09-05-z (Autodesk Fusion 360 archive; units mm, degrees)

design "09-05-z" references "09-PIN", "09-KOTEI", "09-KADOU"
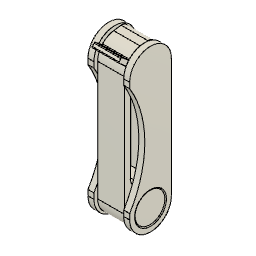
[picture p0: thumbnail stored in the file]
component_insert "コンポーネントの挿入1" alignOffsetZ 0
ground "固定"
component_insert "コンポーネントの挿入2"
joint "アセンブリ1" alignAngle 0 alignOffsetX 0 alignOffsetY 0 alignOffsetZ 0
component_insert "コンポーネントの挿入3"
joint "アセンブリ2" alignAngle 0 alignOffsetX 0 alignOffsetY 0 alignOffsetZ 0
component_insert "コンポーネントの挿入4"
joint "アセンブリ4" alignAngle 0 alignOffsetX 0 alignOffsetY 0 alignOffsetZ 0

design "09-KADOU"
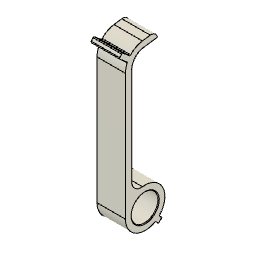
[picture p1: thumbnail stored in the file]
sketch "スケッチ1" plane through (0, 0, 0) normal (1, 0, 0) x axis (0, 0, -1)
  circle C1 centre (0, 0) radius 6.25
  point P1 (0, 0)
  point P2 (0, 0)
  coincident P1 P2
  dimension "d1" diameter C1 = 12.5
extrude "押し出し1" new body sketch "スケッチ1" distance 9
sketch "スケッチ2" plane through (0, 0, 0) normal (1, 0, 0) x axis (0, 0, -1)
  line L1 (-4.25, 0) -> (-4.25, 40)
  line L2 (-6.25, 0) -> (-4.25, 0)
  line L3 (-6.25, 40) -> (-6.25, 0)
  line L4 (3.8647, 44.8349) -> (-0.5915, 44.2086)
  line L5 (3.5864, 46.8155) -> (3.8647, 44.8349)
  line L6 (-0.8698, 46.1892) -> (3.5864, 46.8155)
  circle C1 centre (0, 0) radius 6.25
  arc A1 centre (0, 40) radius 4.25 clockwise from (-4.25, 40) to (-0.5915, 44.2086)
  arc A2 centre (0, 40) radius 6.25 clockwise from (-6.25, 40) to (-0.8698, 46.1892)
  point P1 (0, 0)
  point P8 (0, 40)
  point P12 (0, 40)
  vertical L1
  horizontal L2
  vertical L3
  coincident P1 L2
  tangent L3 C1
  perpendicular L4 L5
  perpendicular L5 L6
  coincident P8 P12
  vertical P1 P8
  tangent L1 A1
  tangent A1 L4
  tangent L3 A2
  dimension "d5" distance L1 L3 = 2
  dimension "d18" distance L4 L6 = 2
  dimension "d21" distance P8 L5 = 4.5
  dimension "d22" angle L1 L4 = 98
  dimension "d54" distance P1 P12 = 40
extrude "押し出し2" add sketch "スケッチ2" profile of L1 L3 C1 distance 9
sketch "スケッチ4" plane through (0, 0, 0) normal (1, 0, 0) x axis (0, 0, -1)
  line L1 (5.3033, -5.3033) -> (0, 0)
  line L2 (4.2426, -6.364) -> (5.3033, -5.3033)
  line L3 (-1.0607, -1.0607) -> (4.2426, -6.364)
  line L4 (0, 0) -> (-1.0607, -1.0607)
  line L5 (-22.5, 0) -> (-1.75, 0)
  point P1 (0, 0)
  point P2 (0, 0)
  perpendicular L1 L2
  parallel L1 L3
  parallel L2 L4
  coincident P1 P2
  dimension "d24" angle L1 L5 = 45
  dimension "d25" distance L2 L4 = 7.5
  dimension "d26" distance L1 L3 = 1.5
extrude "押し出し4" add sketch "スケッチ4" profile of L1 L2 L3 L4 distance 9
joint_origin "JointOrigin1" OffsetX 0 OffsetY 0 OffsetZ 0 AngleZ 0
sketch "スケッチ5" plane through (0, 0, 0) normal (1, 0, 0) x axis (0, 0, -1)
  line L1 (0, 40) -> (-7.2774, 46.1065)
  line L2 (-0.9642, 38.8509) -> (0, 40)
  line L3 (-8.2416, 44.9574) -> (-0.9642, 38.8509)
  line L4 (-7.2774, 46.1065) -> (-8.2416, 44.9574)
  line L5 (0, 22.5) -> (0, 1.75)
  arc A1 centre (0, 40) radius 4.25 clockwise from (-4.25, 40) to (-0.5915, 44.2086)
  point P3 (0, 40)
  point P8 (0, 40)
  perpendicular L1 L2
  parallel L1 L3
  parallel L2 L4
  coincident P3 P8
  dimension "d33" angle L1 L5 = 50
  dimension "d34" distance L1 L3 = 1.5
  dimension "d35" distance L2 L4 = 9.5
extrude "押し出し5" add sketch "スケッチ5" profile of L1 L3 L4 A1 distance 9
fillet "フィレット3" radius 2
sketch "スケッチ6" plane through (0, 43.4339, 6.1042) normal (0, -0.9903, -0.1392) x axis (-1, 0, 0)
  line L1 (-4.5, 10.0669) -> (4.5, 10.0669)
  line L2 (-4.5, 5.5669) -> (-4.5, 10.0669)
  line L3 (4.5, 5.5669) -> (-4.5, 5.5669)
  line L4 (4.5, 10.0669) -> (4.5, 5.5669)
  circle C1 centre (0, 8.0669) radius 0.75
  point P1 (0, 0)
  point P6 (0, 8.0669)
  vertical P1 P6
  dimension "d40" distance L1 P6 = 2
  dimension "d41" diameter C1 = 1.5
extrude "押し出し6" add sketch "スケッチ6" profile of C1 along normal blind 0.7
fillet "フィレット4" radius 0.6
fillet "フィレット5" radius 3
fillet "フィレット6" radius 0.3
hole "穴" HoleDepth 9 HoleDiameter 8.5 TipAngle 118
chamfer "面取り" distance 0.2

design "09-PIN"
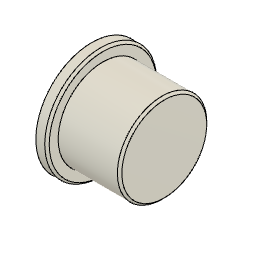
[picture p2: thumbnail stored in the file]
sketch "スケッチ" plane through (0, 0, 0) normal (0, 0, 1) x axis (1, 0, 0)
  line L1 (0, 5) -> (0, 0)
  line L2 (1, 5) -> (0, 5)
  line L3 (1, 4) -> (1, 5)
  line L4 (6.5, 4) -> (1, 4)
  line L5 (6.5, 0) -> (6.5, 4)
  line L6 (0, 0) -> (6.5, 0)
  point P1 (0, 0)
  point P2 (0, 0)
  point P8 (0, 0)
  point P3 (0, 5)
  point P4 (1, 5)
  point P5 (1, 4)
  point P6 (6.5, 4)
  coincident P1 P2
  vertical L1
  perpendicular L1 L2
  perpendicular L2 L3
  perpendicular L3 L4
  perpendicular L4 L5
  coincident P1 P8
  horizontal L6
  dimension "d1" = 8
  dimension "d2" = 10
  dimension "d3" distance P3 P4 = 1
  dimension "d4" distance P5 P6 = 5.5
revolve "回転" sketch "スケッチ" AlongAngle 360
chamfer "面取り" distance 0.2

design "09-KOTEI"
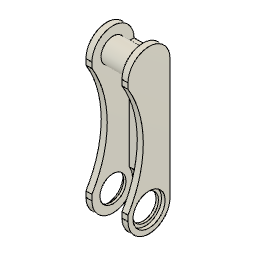
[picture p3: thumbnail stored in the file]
sketch "スケッチ1" plane through (0, 0, 0) normal (1, 0, 0) x axis (0, 0, -1)
  circle C1 centre (0, 40) radius 4
  point P1 (0, 0)
  point P2 (0, 40)
  vertical P1 P2
  dimension "d1" diameter C1 = 8
  dimension "d29" distance P1 P2 = 40
extrude "押し出し1" new body sketch "スケッチ1" + "スケッチ5" profile of S1:C1 distance 10
sketch "スケッチ2" plane through (5, 0, 0) normal (1, 0, 0) x axis (0, 0, -1)
  line L1 (-7, 0) -> (-7, 40)
  line L2 (7, 40) -> (7, 0)
  line L3 (0, 0) -> (0, 40)
  circle C1 centre (0, 40) radius 4
  arc A1 centre (0, 0) radius 7 clockwise from (7, 0) to (-7, 0)
  arc A2 centre (0, 40) radius 7 clockwise from (-7, 40) to (7, 40)
  point P7 (0, 40)
  point P9 (0, 40)
  point P8 (0, 0)
  tangent L1 A1
  tangent A1 L2
  parallel L1 L2
  tangent L2 A2
  tangent L1 A2
  vertical L3
  coincident P7 P9
  concentric C1 A2
  dimension "d4" radius A2 = 7
  dimension "d5" distance P7 P8 = 40
extrude "押し出し2" add sketch "スケッチ2" profile of C1 L1 A1 L2 A2 along normal blind 2
mirror "ミラー" sketch "スケッチ5" mirrorStitchTolerance 0.1
sketch "スケッチ3" plane through (0, 0, 0) normal (1, 0, 0) x axis (0, 0, -1)
  line L1 (7, 40) -> (5.4, 40)
  line L2 (7, 0) -> (7, 40)
  line L3 (5.4, 0) -> (7, 0)
  line L4 (5.4, 40) -> (5.4, 0)
  point P3 (7, 40)
  point P6 (7, 40)
  point P4 (7, 0)
  point P7 (7, 0)
  horizontal L1
  vertical L2
  horizontal L3
  vertical L4
  coincident P3 P6
  coincident P4 P7
  dimension "d10" distance L2 L4 = 1.6
extrude "押し出し3" add sketch "スケッチ3" distance 10
sketch "スケッチ4" plane through (0, 0, 0) normal (1, 0, 0) x axis (0, 0, -1)
  circle C1 centre (-36.9324, 20) radius 35
  arc A1 centre (0, 40) radius 7 clockwise from (-7, 40) to (7, 40)
  arc A2 centre (0, 0) radius 7 clockwise from (7, 0) to (-7, 0)
  tangent C1 A1
  tangent C1 A2
  dimension "d13" diameter C1 = 70
extrude "押し出し4" cut sketch "スケッチ4" profile of C1 no distance stored
sketch "スケッチ5" plane through (0, 0, 0) normal (1, 0, 0) x axis (0, 0, -1)
  circle C1 centre (0, 0) radius 6.5
  arc A1 centre (0, 0) radius 7 clockwise from (7, 0) to (-7, 0)
  concentric C1 A1
  dimension "d15" diameter C1 = 13
extrude "押し出し5" cut sketch "スケッチ5" profile of C1 distance 10
chamfer "面取り" distance 0.2
hole "穴1" HoleDepth 2 HoleDiameter 8.7 TipAngle 118 CBDepth 1.2 CBDiameter 10.7
hole "穴2" HoleDepth 2 HoleDiameter 8.7 TipAngle 118 CBDepth 1.2 CBDiameter 10.7
joint_origin "JointOrigin1" sketch "スケッチ5" OffsetX 0 OffsetY 0 OffsetZ 0 AngleZ 0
